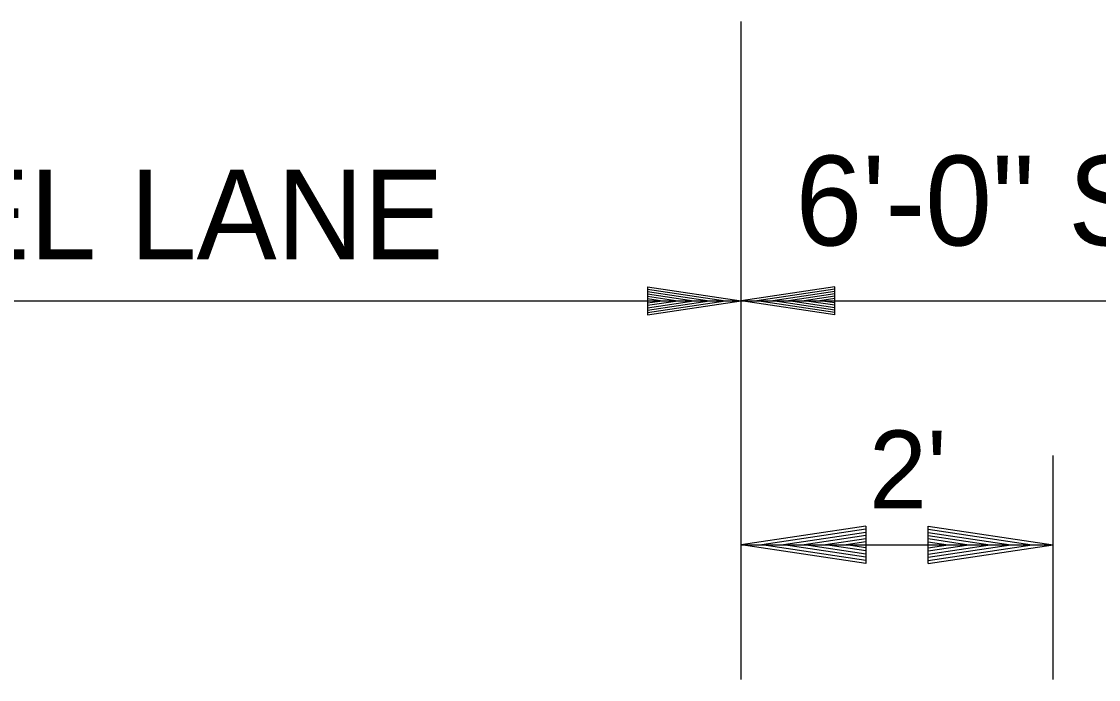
# Model space of a CAD drawing. Extents: x 1364961 to 1365294, y 367927 to 368034.
# Drawn here: x 1365224.86 to 1365231.77, y 367972.63 to 367976.85 of the extents above; entities that cross this region are included whole.
import ezdxf

# ---------------------------------------------------------------- set-up
doc = ezdxf.new("R2010")
doc.units = 0
doc.layers.add('Default', color=7, linetype='Continuous')

msp = doc.modelspace()

# ---------------------------------------------------------------- linework, layer by layer
at = {"layer": 'Default'}
for p, q in [((1365229.476, 367972.6284), (1365229.476, 367976.8499)), ((1365228.876, 367975.1485), (1365229.476, 367975.0585)), ((1365228.876, 367975.1485), (1365228.876, 367974.9685)), ((1365228.876, 367975.1335), (1365229.376, 367975.0585)), ((1365228.876, 367975.1185), (1365229.273, 367975.0585)), ((1365230.076, 367975.1485), (1365229.476, 367975.0585)), ((1365230.076, 367975.1485), (1365229.476, 367975.0585)), ((1365230.076, 367975.1335), (1365229.576, 367975.0585)), ((1365230.076, 367975.1335), (1365229.576, 367975.0585)), ((1365230.076, 367975.1185), (1365229.679, 367975.0585)), ((1365230.076, 367975.1185), (1365229.679, 367975.0585)), ((1365230.076, 367974.9685), (1365230.076, 367975.1485)), ((1365230.076, 367974.9685), (1365230.076, 367975.1485)), ((1365217.487, 367975.0585), (1365229.476, 367975.0585)), ((1365228.876, 367975.1035), (1365229.173, 367975.0585)), ((1365228.876, 367975.0875), (1365229.071, 367975.0585)), ((1365228.876, 367975.0725), (1365228.971, 367975.0585)), ((1365228.876, 367974.9685), (1365229.476, 367975.0585)), ((1365228.876, 367975.0295), (1365229.071, 367975.0585)), ((1365228.876, 367974.9985), (1365229.273, 367975.0585)), ((1365228.876, 367974.9835), (1365229.376, 367975.0585)), ((1365228.876, 367975.0135), (1365229.173, 367975.0585)), ((1365228.876, 367975.0445), (1365228.971, 367975.0585)), ((1365230.076, 367974.9685), (1365229.476, 367975.0585)), ((1365230.076, 367974.9685), (1365229.476, 367975.0585)), ((1365229.476, 367975.0585), (1365235.476, 367975.0585)), ((1365230.076, 367974.9835), (1365229.576, 367975.0585)), ((1365230.076, 367974.9835), (1365229.576, 367975.0585)), ((1365230.076, 367974.9985), (1365229.679, 367975.0585)), ((1365230.076, 367974.9985), (1365229.679, 367975.0585)), ((1365230.076, 367975.1035), (1365229.779, 367975.0585)), ((1365230.076, 367975.1035), (1365229.779, 367975.0585)), ((1365230.076, 367975.0135), (1365229.779, 367975.0585)), ((1365230.076, 367975.0135), (1365229.779, 367975.0585)), ((1365230.076, 367975.0875), (1365229.881, 367975.0585)), ((1365230.076, 367975.0875), (1365229.881, 367975.0585)), ((1365230.076, 367975.0295), (1365229.881, 367975.0585)), ((1365230.076, 367975.0295), (1365229.881, 367975.0585)), ((1365230.076, 367975.0725), (1365229.981, 367975.0585)), ((1365230.076, 367975.0725), (1365229.981, 367975.0585)), ((1365230.076, 367975.0445), (1365229.981, 367975.0585)), ((1365230.076, 367975.0445), (1365229.981, 367975.0585)), ((1365231.476, 367972.6284), (1365231.476, 367974.0645)), ((1365230.276, 367973.6127), (1365229.476, 367973.4927)), ((1365230.276, 367973.5927), (1365229.6096, 367973.4927)), ((1365230.276, 367973.6127), (1365230.276, 367973.3727)), ((1365230.676, 367973.6127), (1365231.476, 367973.4927)), ((1365230.676, 367973.3727), (1365230.676, 367973.6127)), ((1365230.676, 367973.5927), (1365231.3424, 367973.4927)), ((1365230.276, 367973.5723), (1365229.7472, 367973.4927)), ((1365230.276, 367973.5523), (1365229.8804, 367973.4927)), ((1365230.276, 367973.5315), (1365230.016, 367973.4927)), ((1365230.676, 367973.5723), (1365231.2048, 367973.4927)), ((1365230.676, 367973.5523), (1365231.0716, 367973.4927)), ((1365230.676, 367973.5319), (1365230.936, 367973.4927)), ((1365229.476, 367973.4927), (1365231.476, 367973.4927)), ((1365230.276, 367973.3727), (1365229.476, 367973.4927)), ((1365230.276, 367973.3927), (1365229.6096, 367973.4927)), ((1365230.276, 367973.4131), (1365229.7472, 367973.4927)), ((1365230.276, 367973.4331), (1365229.8804, 367973.4927)), ((1365230.276, 367973.4535), (1365230.016, 367973.4927)), ((1365230.276, 367973.5115), (1365230.1496, 367973.4927)), ((1365230.276, 367973.4739), (1365230.1496, 367973.4927)), ((1365230.676, 367973.5115), (1365230.8024, 367973.4927)), ((1365230.676, 367973.3727), (1365231.476, 367973.4927)), ((1365230.676, 367973.4539), (1365230.936, 367973.4927)), ((1365230.676, 367973.4131), (1365231.2048, 367973.4927)), ((1365230.676, 367973.3927), (1365231.3424, 367973.4927)), ((1365230.676, 367973.4331), (1365231.0716, 367973.4927)), ((1365230.676, 367973.4739), (1365230.8024, 367973.4927))]:
    msp.add_line(p, q, dxfattribs=at)

# ---------------------------------------------------------------- texts
for s, height, p in [('6\'-0" SHLDR.', 0.576, (1365229.8241, 367975.4133)), ('12\'-0" ACCEL/DECEL LANE', 0.576, (1365217.8148, 367975.3238)), ("2'", 0.5, (1365230.2953, 367973.7258))]:
    msp.add_text(s, height=height, dxfattribs=at).set_placement(p)

doc.saveas('drawing.dxf')
